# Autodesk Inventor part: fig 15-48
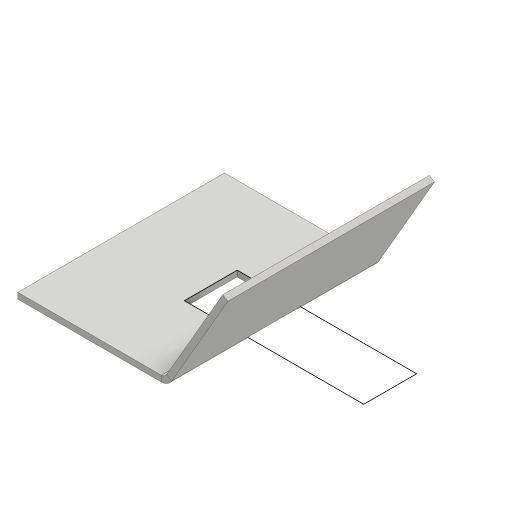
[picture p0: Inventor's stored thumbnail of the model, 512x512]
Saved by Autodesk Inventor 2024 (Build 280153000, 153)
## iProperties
Created: 2015-07
Part Number: fig 15-48
Material: Generic
Document SubType Name: Sheet Metal
Designer: Sandeep
Density: 1 g/cm^3
Sheet Metal Rule: Default_mm
Appearance: Default
Author: Sandeep
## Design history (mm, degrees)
node "Face1"
  sketch "Sketch1"
    geometry: L1 (-12.609, 8.313)-(0, 8.313); L2 (0, 8.313)-(0, -9.006); L3 (0, -9.006)-(-12.609, -9.006); L4 (-12.609, -9.006)-(-12.609, 8.313); 1 further point
    constraints: 8 end point, 2 parallel, 1 horizontal, 1 perpendicular
node "Flange1"
sketch "Sketch3"
  geometry: L1 (9.998, 1.795)-(-5.034, 1.795); L2 (-5.034, 1.795)-(-5.034, -2.633); L3 (-5.034, -2.633)-(9.998, -2.633); L4 (9.998, -2.633)-(9.998, 1.795); 1 further point
  constraints: 8 end point, 2 parallel, 1 horizontal, 1 perpendicular
cut "Cut1" sketch "Sketch3" dims "d11" = 0.5 (= Thickness), "d12" = 0
body "Solid1"
face "Plate1" dims "d13" = 0.5 (= Thickness)
sketch "Sketch2"
  geometry: L1 (0, 10)-(-17.319, 10); L2 (-17.319, 10)-(-17.319, 0); 1 other entity
  constraints: 4 end point, 4 other
face "Plate2" dims "d1" = 0.5 (= BendReliefWidth), "d2" = 0.25 (= BendReliefDepth), "d3" = 1 (= MinimumRemnant), "d4" = 0.5 (= BendRadius), "d5" = 10, "d6" = 60 deg, "d7" = 0.5 (= BendRadius), "d8" = 2 (= CornerReliefSize), "d9" = 0.5 (= GapSize), "d10" = 0.5 (= JacobiRadiusSize), "d13" = 0.5 (= Thickness), "SeamGap" = 0.01
bend "Bend1" dims "d1" = 0.5 (= BendReliefWidth), "d2" = 0.25 (= BendReliefDepth), "d3" = 1 (= MinimumRemnant), "d4" = 0.5 (= BendRadius), "d5" = 10, "d6" = 60 deg, "d7" = 0.5 (= BendRadius), "d13" = 0.5 (= Thickness), "SeamGap" = 0.01
feature "Corner1" dims "d5" = 10, "d6" = 60 deg, "d8" = 2 (= CornerReliefSize), "d9" = 0.5 (= GapSize), "d10" = 0.5 (= JacobiRadiusSize)
other parameters: "Thickness" = 0.5, "BendRadius" = 0.5 (= Thickness), "BendReliefWidth" = 0.5 (= Thickness), "BendReliefDepth" = 0.25 (= 0.5 x Thickness), "CornerReliefSize" = 2 (= 4 x Thickness), "MinimumRemnant" = 1 (= 2 x Thickness), "TransitionRadius" = 0.5 (= BendRadius), "JacobiRadiusSize" = 0.5 (= BendRadius), "GapSize" = 0.5 (= Thickness), "d0" = 0.5 (= BendRadius)
